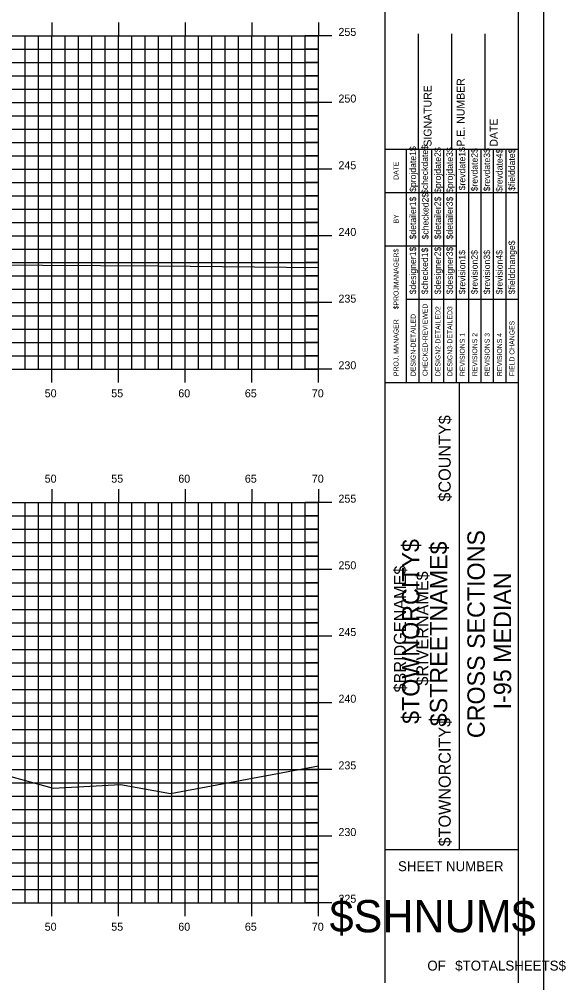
# Model space of a CAD drawing. Extents: x 1168600 to 1177589, y 610178 to 611246.
# Drawn here: x 1172004.6 to 1172045.6, y 610271.8 to 610344 of the extents above; entities that cross this region are included whole.
import ezdxf

# ---------------------------------------------------------------- set-up
doc = ezdxf.new("R2010")
doc.units = 0
for name, color, linetype in [('_Station Equation', 7, 'Continuous'), ('BORDER', 7, 'Continuous'), ('BRIDGE_TITLE', 7, 'Continuous'), ('H_V ANNOTATION', 7, 'Continuous'), ('HIGHWAY_TITLE', 7, 'Continuous'), ('MAJOR', 7, 'Continuous'), ('MINOR', 7, 'Continuous'), ('PLOT BOUNDARY', 7, 'Continuous')]:
    doc.layers.add(name, color=color, linetype=linetype)

msp = doc.modelspace()

# ---------------------------------------------------------------- linework, layer by layer
at = {"layer": '_Station Equation'}
for points in [[(1171953.396, 610334.023), (1171958.071, 610333.867), (1171958.65, 610333.839), (1171960.709, 610333.74), (1171961.097, 610333.634), (1171962.561, 610333.283), (1171982.997, 610327.775), (1171992.143, 610325.272), (1171999.787, 610325.9), (1172001.967, 610325.631), (1172014.976, 610325.554), (1172027.01, 610325.445)], [(1171951.154, 610298.607), (1171955.964, 610298.471), (1171956.444, 610298.455), (1171960.971, 610298.303), (1171961.393, 610298.285), (1171963.766, 610298.184), (1171964.095, 610298.103), (1171965.534, 610297.758), (1171978.579, 610294.247), (1172007.103, 610286.381), (1172012.167, 610286.676), (1172015.912, 610285.99), (1172027.01, 610288.06)]]:
    msp.add_lwpolyline(points, dxfattribs=at)
at = {"layer": 'BORDER'}
for p, q in [((1172032.011, 610271.804), (1172032.011, 610376.804)), ((1172042.011, 610271.804), (1172042.011, 610376.804)), ((1172034.511, 610334.304), (1172034.511, 610342.952)), ((1172037.011, 610334.304), (1172037.011, 610342.952)), ((1172039.511, 610334.304), (1172039.511, 610342.952)), ((1172032.011, 610334.304), (1172042.011, 610334.304)), ((1172032.011, 610316.804), (1172042.011, 610316.804)), ((1172037.602, 610281.804), (1172037.602, 610316.804)), ((1172032.011, 610281.804), (1172042.011, 610281.804))]:
    msp.add_line(p, q, dxfattribs=at)
for points in [[(1172033.626, 610331.054), (1172033.626, 610334.304)], [(1172034.558, 610316.807), (1172034.558, 610334.304)], [(1172035.49, 610334.304), (1172035.49, 610316.807)], [(1172036.421, 610316.807), (1172036.421, 610334.304)], [(1172037.353, 610316.807), (1172037.353, 610334.304)], [(1172038.285, 610316.807), (1172038.285, 610334.304)], [(1172039.217, 610316.807), (1172039.217, 610334.304)], [(1172040.148, 610316.807), (1172040.148, 610334.304)], [(1172041.08, 610316.807), (1172041.08, 610334.304)], [(1172033.626, 610316.807), (1172033.626, 610333.598)], [(1172032.011, 610331.054), (1172042.011, 610331.054)], [(1172032.011, 610327.054), (1172033.626, 610327.054)], [(1172033.626, 610327.054), (1172037.352, 610327.054)], [(1172033.626, 610323.054), (1172042.011, 610323.054)]]:
    msp.add_lwpolyline(points, dxfattribs=at)
at = {"layer": 'MAJOR'}
for p, q in [((1172007.01, 610343.803), (1172007.01, 610342.801)), ((1172012.01, 610343.803), (1172012.01, 610342.801)), ((1172017.01, 610343.803), (1172017.01, 610342.801)), ((1172022.01, 610343.803), (1172022.01, 610342.801)), ((1172027.01, 610343.803), (1172027.01, 610342.801)), ((1171887.01, 610342.801), (1172027.01, 610342.801)), ((1171887.01, 610342.801), (1172027.01, 610342.801)), ((1172007.01, 610317.801), (1172007.01, 610342.801)), ((1172012.01, 610317.801), (1172012.01, 610342.801)), ((1172017.01, 610317.801), (1172017.01, 610342.801)), ((1172022.01, 610317.801), (1172022.01, 610342.801)), ((1172028.012, 610342.801), (1172026.008, 610342.801)), ((1172027.01, 610317.801), (1172027.01, 610342.801)), ((1172027.01, 610317.801), (1172027.01, 610342.801)), ((1171887.01, 610337.801), (1172027.01, 610337.801)), ((1172028.012, 610337.801), (1172026.008, 610337.801)), ((1171887.01, 610332.801), (1172027.01, 610332.801)), ((1172028.012, 610332.801), (1172026.008, 610332.801)), ((1171887.01, 610327.801), (1172027.01, 610327.801)), ((1172028.012, 610327.801), (1172026.008, 610327.801)), ((1171887.01, 610322.801), (1172027.01, 610322.801)), ((1172028.012, 610322.801), (1172026.008, 610322.801)), ((1171887.01, 610317.801), (1172027.01, 610317.801)), ((1171887.01, 610317.801), (1172027.01, 610317.801)), ((1172007.01, 610316.799), (1172007.01, 610317.801)), ((1172012.01, 610316.799), (1172012.01, 610317.801)), ((1172017.01, 610316.799), (1172017.01, 610317.801)), ((1172022.01, 610316.799), (1172022.01, 610317.801)), ((1172028.012, 610317.801), (1172026.008, 610317.801)), ((1172027.01, 610316.799), (1172027.01, 610317.801)), ((1172007.01, 610308.803), (1172007.01, 610307.801)), ((1172012.01, 610308.803), (1172012.01, 610307.801)), ((1172017.01, 610308.803), (1172017.01, 610307.801)), ((1172022.01, 610308.803), (1172022.01, 610307.801)), ((1172027.01, 610308.803), (1172027.01, 610307.801)), ((1171887.01, 610307.801), (1172027.01, 610307.801)), ((1171887.01, 610307.801), (1172027.01, 610307.801)), ((1172007.01, 610277.801), (1172007.01, 610307.801)), ((1172012.01, 610277.801), (1172012.01, 610307.801)), ((1172017.01, 610277.801), (1172017.01, 610307.801)), ((1172022.01, 610277.801), (1172022.01, 610307.801)), ((1172028.012, 610307.801), (1172026.008, 610307.801)), ((1172027.01, 610277.801), (1172027.01, 610307.801)), ((1172027.01, 610277.801), (1172027.01, 610307.801)), ((1171887.01, 610302.801), (1172027.01, 610302.801)), ((1172028.012, 610302.801), (1172026.008, 610302.801)), ((1171887.01, 610297.801), (1172027.01, 610297.801)), ((1172028.012, 610297.801), (1172026.008, 610297.801)), ((1171887.01, 610292.801), (1172027.01, 610292.801)), ((1172028.012, 610292.801), (1172026.008, 610292.801)), ((1171887.01, 610287.801), (1172027.01, 610287.801)), ((1172028.012, 610287.801), (1172026.008, 610287.801)), ((1171887.01, 610282.801), (1172027.01, 610282.801)), ((1172028.012, 610282.801), (1172026.008, 610282.801)), ((1171887.01, 610277.801), (1172027.01, 610277.801)), ((1171887.01, 610277.801), (1172027.01, 610277.801)), ((1172007.01, 610276.799), (1172007.01, 610277.801)), ((1172012.01, 610276.799), (1172012.01, 610277.801)), ((1172017.01, 610276.799), (1172017.01, 610277.801)), ((1172022.01, 610276.799), (1172022.01, 610277.801)), ((1172028.012, 610277.801), (1172026.008, 610277.801)), ((1172027.01, 610276.799), (1172027.01, 610277.801))]:
    msp.add_line(p, q, dxfattribs=at)
at = {"layer": 'MINOR'}
for p, q in [((1172005.01, 610317.801), (1172005.01, 610342.801)), ((1172006.01, 610317.801), (1172006.01, 610342.801)), ((1172008.01, 610317.801), (1172008.01, 610342.801)), ((1172009.01, 610317.801), (1172009.01, 610342.801)), ((1172010.01, 610317.801), (1172010.01, 610342.801)), ((1172011.01, 610317.801), (1172011.01, 610342.801)), ((1172013.01, 610317.801), (1172013.01, 610342.801)), ((1172014.01, 610317.801), (1172014.01, 610342.801)), ((1172015.01, 610317.801), (1172015.01, 610342.801)), ((1172016.01, 610317.801), (1172016.01, 610342.801)), ((1172018.01, 610317.801), (1172018.01, 610342.801)), ((1172019.01, 610317.801), (1172019.01, 610342.801)), ((1172020.01, 610317.801), (1172020.01, 610342.801)), ((1172021.01, 610317.801), (1172021.01, 610342.801)), ((1172023.01, 610317.801), (1172023.01, 610342.801)), ((1172024.01, 610317.801), (1172024.01, 610342.801)), ((1172025.01, 610317.801), (1172025.01, 610342.801)), ((1172026.01, 610317.801), (1172026.01, 610342.801)), ((1171887.01, 610341.801), (1172027.01, 610341.801)), ((1172027.01, 610341.801), (1172026.008, 610341.801)), ((1171887.01, 610340.801), (1172027.01, 610340.801)), ((1172027.01, 610340.801), (1172026.008, 610340.801)), ((1171887.01, 610339.801), (1172027.01, 610339.801)), ((1172027.01, 610339.801), (1172026.008, 610339.801)), ((1171887.01, 610338.801), (1172027.01, 610338.801)), ((1172027.01, 610338.801), (1172026.008, 610338.801)), ((1171887.01, 610336.801), (1172027.01, 610336.801)), ((1172027.01, 610336.801), (1172026.008, 610336.801)), ((1171887.01, 610335.801), (1172027.01, 610335.801)), ((1172027.01, 610335.801), (1172026.008, 610335.801)), ((1171887.01, 610334.801), (1172027.01, 610334.801)), ((1172027.01, 610334.801), (1172026.008, 610334.801)), ((1171887.01, 610333.801), (1172027.01, 610333.801)), ((1172027.01, 610333.801), (1172026.008, 610333.801)), ((1171887.01, 610331.801), (1172027.01, 610331.801)), ((1172027.01, 610331.801), (1172026.008, 610331.801)), ((1171887.01, 610330.801), (1172027.01, 610330.801)), ((1172027.01, 610330.801), (1172026.008, 610330.801)), ((1171887.01, 610329.801), (1172027.01, 610329.801)), ((1172027.01, 610329.801), (1172026.008, 610329.801)), ((1171887.01, 610328.801), (1172027.01, 610328.801)), ((1172027.01, 610328.801), (1172026.008, 610328.801)), ((1171887.01, 610326.801), (1172027.01, 610326.801)), ((1172027.01, 610326.801), (1172026.008, 610326.801)), ((1171887.01, 610325.801), (1172027.01, 610325.801)), ((1172027.01, 610325.801), (1172026.008, 610325.801)), ((1171887.01, 610324.801), (1172027.01, 610324.801)), ((1172027.01, 610324.801), (1172026.008, 610324.801)), ((1171887.01, 610323.801), (1172027.01, 610323.801)), ((1172027.01, 610323.801), (1172026.008, 610323.801)), ((1171887.01, 610321.801), (1172027.01, 610321.801)), ((1172027.01, 610321.801), (1172026.008, 610321.801)), ((1171887.01, 610320.801), (1172027.01, 610320.801)), ((1172027.01, 610320.801), (1172026.008, 610320.801)), ((1171887.01, 610319.801), (1172027.01, 610319.801)), ((1172027.01, 610319.801), (1172026.008, 610319.801)), ((1171887.01, 610318.801), (1172027.01, 610318.801)), ((1172027.01, 610318.801), (1172026.008, 610318.801)), ((1172005.01, 610277.801), (1172005.01, 610307.801)), ((1172006.01, 610277.801), (1172006.01, 610307.801)), ((1172008.01, 610277.801), (1172008.01, 610307.801)), ((1172009.01, 610277.801), (1172009.01, 610307.801)), ((1172010.01, 610277.801), (1172010.01, 610307.801)), ((1172011.01, 610277.801), (1172011.01, 610307.801)), ((1172013.01, 610277.801), (1172013.01, 610307.801)), ((1172014.01, 610277.801), (1172014.01, 610307.801)), ((1172015.01, 610277.801), (1172015.01, 610307.801)), ((1172016.01, 610277.801), (1172016.01, 610307.801)), ((1172018.01, 610277.801), (1172018.01, 610307.801)), ((1172019.01, 610277.801), (1172019.01, 610307.801)), ((1172020.01, 610277.801), (1172020.01, 610307.801)), ((1172021.01, 610277.801), (1172021.01, 610307.801)), ((1172023.01, 610277.801), (1172023.01, 610307.801)), ((1172024.01, 610277.801), (1172024.01, 610307.801)), ((1172025.01, 610277.801), (1172025.01, 610307.801)), ((1172026.01, 610277.801), (1172026.01, 610307.801)), ((1171887.01, 610306.801), (1172027.01, 610306.801)), ((1172027.01, 610306.801), (1172026.008, 610306.801)), ((1171887.01, 610305.801), (1172027.01, 610305.801)), ((1172027.01, 610305.801), (1172026.008, 610305.801)), ((1171887.01, 610304.801), (1172027.01, 610304.801)), ((1172027.01, 610304.801), (1172026.008, 610304.801)), ((1171887.01, 610303.801), (1172027.01, 610303.801)), ((1172027.01, 610303.801), (1172026.008, 610303.801)), ((1171887.01, 610301.801), (1172027.01, 610301.801)), ((1172027.01, 610301.801), (1172026.008, 610301.801)), ((1171887.01, 610300.801), (1172027.01, 610300.801)), ((1172027.01, 610300.801), (1172026.008, 610300.801)), ((1171887.01, 610299.801), (1172027.01, 610299.801)), ((1172027.01, 610299.801), (1172026.008, 610299.801)), ((1171887.01, 610298.801), (1172027.01, 610298.801)), ((1172027.01, 610298.801), (1172026.008, 610298.801)), ((1171887.01, 610296.801), (1172027.01, 610296.801)), ((1172027.01, 610296.801), (1172026.008, 610296.801)), ((1171887.01, 610295.801), (1172027.01, 610295.801)), ((1172027.01, 610295.801), (1172026.008, 610295.801)), ((1171887.01, 610294.801), (1172027.01, 610294.801)), ((1172027.01, 610294.801), (1172026.008, 610294.801)), ((1171887.01, 610293.801), (1172027.01, 610293.801)), ((1172027.01, 610293.801), (1172026.008, 610293.801)), ((1171887.01, 610291.801), (1172027.01, 610291.801)), ((1172027.01, 610291.801), (1172026.008, 610291.801)), ((1171887.01, 610290.801), (1172027.01, 610290.801)), ((1172027.01, 610290.801), (1172026.008, 610290.801)), ((1171887.01, 610289.801), (1172027.01, 610289.801)), ((1172027.01, 610289.801), (1172026.008, 610289.801)), ((1171887.01, 610288.801), (1172027.01, 610288.801)), ((1172027.01, 610288.801), (1172026.008, 610288.801)), ((1171887.01, 610286.801), (1172027.01, 610286.801)), ((1172027.01, 610286.801), (1172026.008, 610286.801)), ((1171887.01, 610285.801), (1172027.01, 610285.801)), ((1172027.01, 610285.801), (1172026.008, 610285.801)), ((1171887.01, 610284.801), (1172027.01, 610284.801)), ((1172027.01, 610284.801), (1172026.008, 610284.801)), ((1171887.01, 610283.801), (1172027.01, 610283.801)), ((1172027.01, 610283.801), (1172026.008, 610283.801)), ((1171887.01, 610281.801), (1172027.01, 610281.801)), ((1172027.01, 610281.801), (1172026.008, 610281.801)), ((1171887.01, 610280.801), (1172027.01, 610280.801)), ((1172027.01, 610280.801), (1172026.008, 610280.801)), ((1171887.01, 610279.801), (1172027.01, 610279.801)), ((1172027.01, 610279.801), (1172026.008, 610279.801)), ((1171887.01, 610278.801), (1172027.01, 610278.801)), ((1172027.01, 610278.801), (1172026.008, 610278.801))]:
    msp.add_line(p, q, dxfattribs=at)
at = {"layer": 'PLOT BOUNDARY'}
msp.add_lwpolyline([(1171873.917, 610268.742), (1172043.917, 610268.742), (1172043.917, 610378.742), (1171873.917, 610378.742)], close=True, dxfattribs=at)

# ---------------------------------------------------------------- texts
at = {"layer": 'BORDER'}
for s, height, rotation, p in [('P.E. NUMBER', 0.59055, 90, (1172037.971, 610334.496)), ('SIGNATURE', 0.5906, 90, (1172035.491, 610334.496)), ('DATE', 0.5906, 90, (1172040.452, 610334.496)), ('$projdate1$', 0.48455, 90, (1172034.334, 610331.104)), ('$checkdate$', 0.48455, 90, (1172035.228, 610330.947)), ('$projdate2$', 0.48455, 90, (1172036.197, 610331.026)), ('$projdate3$', 0.48455, 90, (1172037.091, 610331.026)), ('$revdate1$', 0.4845, 90, (1172038.023, 610331.222)), ('$revdate2$', 0.4845, 90, (1172038.955, 610331.144)), ('$revdate3$', 0.4845, 90, (1172039.886, 610331.144)), ('$revdate4$', 0.4845, 90, (1172040.818, 610331.104)), ('$fielddate$', 0.48455, 90, (1172041.75, 610331.183)), ('DATE', 0.3714, 90, (1172033.015, 610332.01)), ('$checked2$', 0.4845, 90, (1172035.265, 610327.539)), ('$detailer1$', 0.48455, 90, (1172034.334, 610327.539)), ('$detailer2$', 0.48455, 90, (1172036.197, 610327.539)), ('$detailer3$', 0.48455, 90, (1172037.091, 610327.539)), ('BY', 0.3714, 90, (1172033.015, 610328.739)), ('$fieldchange$', 0.48455, 90, (1172041.75, 610323.427)), ('$PROJMANAGER$', 0.37275, 90, (1172033.015, 610322.299)), ('$designer1$', 0.48455, 90, (1172034.334, 610323.427)), ('$checked1$', 0.4845, 90, (1172035.228, 610323.427)), ('$designer2$', 0.48455, 90, (1172036.197, 610323.427)), ('$designer3$', 0.48455, 90, (1172037.091, 610323.427)), ('$revision1$', 0.48455, 90, (1172038.023, 610323.427)), ('$revision2$', 0.48455, 90, (1172038.955, 610323.427)), ('$revision3$', 0.48455, 90, (1172039.886, 610323.427)), ('$revision4$', 0.48455, 90, (1172040.818, 610323.427)), ('CHECKED-REVIEWED', 0.37275, 90, (1172035.192, 610317.292)), ('DESIGN2-DETAILED2', 0.37275, 90, (1172036.161, 610317.292)), ('DESIGN3-DETAILED3', 0.37275, 90, (1172037.055, 610317.292)), ('DESIGN-DETAILED', 0.37275, 90, (1172034.297, 610317.292)), ('PROJ. MANAGER', 0.37275, 90, (1172033.015, 610317.292)), ('FIELD CHANGES', 0.37275, 90, (1172041.713, 610317.292)), ('REVISIONS 1', 0.37275, 90, (1172037.987, 610317.292)), ('REVISIONS 2', 0.37275, 90, (1172038.918, 610317.292)), ('REVISIONS 3', 0.37275, 90, (1172039.85, 610317.292)), ('REVISIONS 4', 0.37275, 90, (1172040.782, 610317.292)), ('CROSS SECTIONS', 1.30428, 90, (1172039.486, 610290.143)), ('I-95 MEDIAN', 1.30428, 90, (1172041.465, 610292.302)), ('SHEET NUMBER', 0.74527, 360, (1172032.976, 610280.168)), ('$SHNUM$', 2.4194, 360, (1172027.844, 610275.584)), ('OF', 0.7453, 360, (1172035.178, 610272.714)), ('$TOTALSHEETS$', 0.74527, 360, (1172037.267, 610272.714))]:
    msp.add_text(s, height=height, rotation=rotation, dxfattribs=at).set_placement(p)
at = {"layer": 'BRIDGE_TITLE'}
for s, height, p in [('$COUNTY$', 0.9072, (1172036.931, 610307.883)), ('$BRIDGENAME$', 0.90716, (1172033.577, 610293.572)), ('$RIVERNAME$', 0.90716, (1172035.254, 610294.087)), ('$TOWNORCITY$', 0.90716, (1172036.931, 610282.025))]:
    msp.add_text(s, height=height, rotation=90, dxfattribs=at).set_placement(p)
at = {"layer": 'H_V ANNOTATION'}
for s, p in [('255', (1172028.51, 610342.801)), ('250', (1172028.51, 610337.801)), ('245', (1172028.51, 610332.801)), ('240', (1172028.51, 610327.801)), ('235', (1172028.51, 610322.801)), ('230', (1172028.51, 610317.801)), ('50', (1172006.475, 610315.701)), ('55', (1172011.467, 610315.701)), ('60', (1172016.497, 610315.701)), ('65', (1172021.489, 610315.701)), ('70', (1172026.513, 610315.701)), ('50', (1172006.475, 610309.301)), ('55', (1172011.467, 610309.301)), ('60', (1172016.497, 610309.301)), ('65', (1172021.489, 610309.301)), ('70', (1172026.513, 610309.301)), ('255', (1172028.51, 610307.801)), ('250', (1172028.51, 610302.801)), ('245', (1172028.51, 610297.801)), ('240', (1172028.51, 610292.801)), ('235', (1172028.51, 610287.801)), ('230', (1172028.51, 610282.801)), ('225', (1172028.51, 610277.801)), ('50', (1172006.475, 610275.701)), ('55', (1172011.467, 610275.701)), ('60', (1172016.497, 610275.701)), ('65', (1172021.489, 610275.701)), ('70', (1172026.513, 610275.701))]:
    msp.add_text(s, height=0.6, dxfattribs=at).set_placement(p)
at = {"layer": 'HIGHWAY_TITLE'}
for s, p in [('$TOWNORCITY$', (1172034.583, 610291.212)), ('$STREETNAME$', (1172036.67, 610291.032))]:
    msp.add_text(s, height=1.30428, rotation=90, dxfattribs=at).set_placement(p)

doc.saveas('drawing.dxf')
